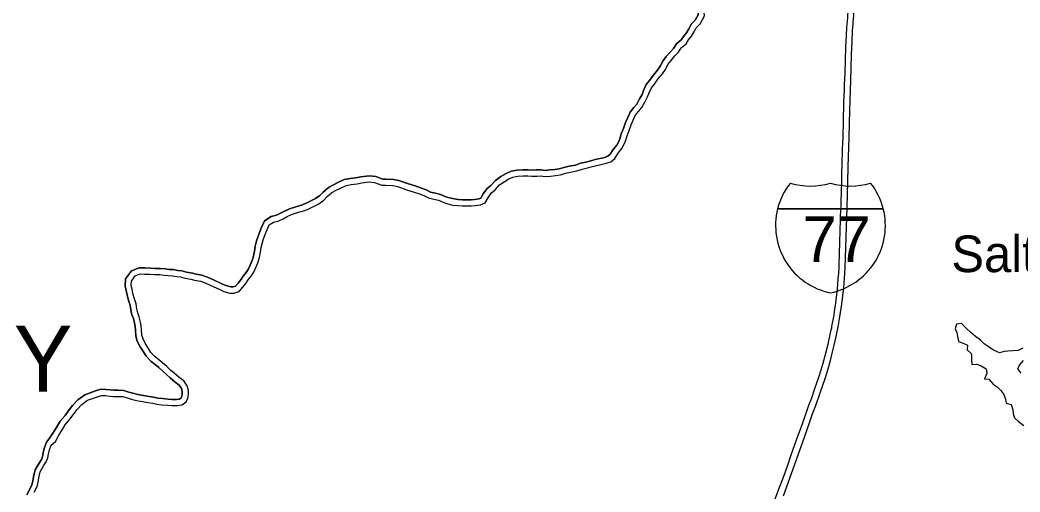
# Model space of a CAD drawing. Extents: x -29.6 to 34, y 0 to 22.
# Drawn here: x -24.702 to -22.275, y 9.402 to 10.547 of the extents above; entities that cross this region are included whole.
import ezdxf

# ---------------------------------------------------------------- set-up
doc = ezdxf.new("R2010")
doc.units = 0
for name, color, linetype in [('GM_X_Interstate_Route', 7, 'Continuous'), ('GM_X_Interstate_Shield', 7, 'Continuous'), ('GM_X_Major_Lake', 7, 'Continuous'), ('GM_X_Major_Lake_Text', 7, 'Continuous'), ('GM_X_Major_River', 7, 'Continuous'), ('GM_X_Township_Text', 7, 'Continuous')]:
    doc.layers.add(name, color=color, linetype=linetype)

msp = doc.modelspace()

# ---------------------------------------------------------------- linework, layer by layer
at = {"layer": 'GM_X_Interstate_Route'}
for points in [[(-22.6803, 10.5356), (-22.6799, 10.5406), (-22.6784, 10.5577), (-22.678, 10.562), (-22.6751, 10.5887), (-22.6714, 10.6173), (-22.6679, 10.6412), (-22.664, 10.6646), (-22.6599, 10.6866), (-22.6555, 10.7085), (-22.6498, 10.7343), (-22.6441, 10.758), (-22.6383, 10.7799), (-22.6335, 10.7978), (-22.627, 10.8194), (-22.6199, 10.8434), (-22.6114, 10.8677), (-22.6038, 10.8899)], [(-22.6947, 10.5356), (-22.6933, 10.5523), (-22.6926, 10.5587), (-22.6906, 10.5784), (-22.6882, 10.5986), (-22.6874, 10.605), (-22.6836, 10.6332), (-22.6802, 10.6557), (-22.6764, 10.6775), (-22.6716, 10.702), (-22.6662, 10.7271), (-22.6578, 10.7627), (-22.6532, 10.7809)], [(-22.8701, 9.3824), (-22.8592, 9.4114), (-22.8494, 9.4378), (-22.8379, 9.4695), (-22.8309, 9.4893), (-22.8164, 9.5305), (-22.8032, 9.5673), (-22.7872, 9.6122), (-22.7807, 9.6298), (-22.7727, 9.6525), (-22.7633, 9.6802), (-22.7576, 9.6979), (-22.7518, 9.7177), (-22.7465, 9.7385), (-22.7409, 9.7603), (-22.7355, 9.7839), (-22.7331, 9.7948), (-22.732, 9.7999), (-22.7316, 9.8022), (-22.7298, 9.8119), (-22.7286, 9.8188), (-22.727, 9.8268), (-22.7265, 9.8303), (-22.725, 9.8401), (-22.7228, 9.8545), (-22.7213, 9.8672), (-22.7197, 9.8805), (-22.7184, 9.8939), (-22.7172, 9.9066), (-22.7162, 9.9188), (-22.7151, 9.9322), (-22.7142, 9.9467), (-22.7137, 9.9595), (-22.7131, 9.9735), (-22.7128, 9.9869), (-22.7122, 10.0003), (-22.712, 10.0148), (-22.7114, 10.0276), (-22.7113, 10.0422), (-22.7106, 10.0555), (-22.7104, 10.0689), (-22.7097, 10.0852), (-22.7093, 10.0968), (-22.7091, 10.1108), (-22.7084, 10.1242), (-22.7083, 10.1353), (-22.7078, 10.1486), (-22.7075, 10.162), (-22.7072, 10.1789), (-22.7067, 10.1929), (-22.7064, 10.2074), (-22.7058, 10.2208), (-22.7056, 10.2336), (-22.705, 10.2476), (-22.7045, 10.2615), (-22.7043, 10.2749), (-22.7038, 10.29), (-22.7036, 10.3017), (-22.7031, 10.3174), (-22.7028, 10.3308), (-22.7024, 10.3471), (-22.7018, 10.3622), (-22.7014, 10.3773), (-22.7007, 10.3913), (-22.7003, 10.4041), (-22.6998, 10.418), (-22.6989, 10.4495), (-22.6978, 10.4815), (-22.6965, 10.5082), (-22.6952, 10.5291), (-22.6947, 10.5356)], [(-22.8492, 9.3926), (-22.8184, 9.4781), (-22.7974, 9.5373), (-22.7851, 9.5719), (-22.7784, 9.5912), (-22.7723, 9.6075), (-22.7676, 9.6213), (-22.7618, 9.6372), (-22.7583, 9.6473), (-22.7551, 9.6564), (-22.7474, 9.6796), (-22.7409, 9.7008), (-22.7352, 9.7209), (-22.7298, 9.7418), (-22.7259, 9.7582), (-22.7212, 9.7792), (-22.7166, 9.802), (-22.7129, 9.8221), (-22.7104, 9.837), (-22.7073, 9.8577), (-22.7047, 9.8779), (-22.7027, 9.8982), (-22.701, 9.9208), (-22.6996, 9.9452), (-22.6977, 9.9952), (-22.6949, 10.093), (-22.6929, 10.1541), (-22.6919, 10.1908), (-22.69, 10.2618), (-22.6879, 10.3276), (-22.686, 10.3997), (-22.6841, 10.4626), (-22.6828, 10.4946), (-22.6814, 10.5208), (-22.6803, 10.5356)]]:
    msp.add_lwpolyline(points, dxfattribs=at)
at = {"layer": 'GM_X_Interstate_Shield'}
for p, q in [((-22.8631, 10.0888), (-22.607, 10.0888)), ((-22.607, 10.0888), (-22.8631, 10.0888)), ((-22.607, 10.0888), (-22.8631, 10.0888))]:
    msp.add_line(p, q, dxfattribs=at)
for centre, start, end in [((-22.7018, 10.048), 141.669, 165.8066), ((-22.7837, 10.3104), 253.0091, 286.9909), ((-22.6864, 10.3104), 253.0091, 286.9909), ((-22.7683, 10.048), 14.1934, 38.331), ((-22.7018, 10.048), 165.8066, 258.463), ((-22.7683, 10.048), 281.537, 14.1934)]:
    msp.add_arc(centre, 0.1665, start, end, dxfattribs=at)
at = {"layer": 'GM_X_Major_Lake'}
for points in [[(-22.2682, 9.7509), (-22.2799, 9.7451), (-22.2927, 9.7439), (-22.3044, 9.7435), (-22.3136, 9.7423), (-22.3253, 9.7397), (-22.3395, 9.7457), (-22.3502, 9.7527), (-22.362, 9.7615), (-22.3713, 9.7703), (-22.3835, 9.7787), (-22.3949, 9.7883), (-22.406, 9.7992), (-22.4175, 9.8101), (-22.4292, 9.8086), (-22.4323, 9.7976), (-22.4283, 9.7883), (-22.4268, 9.7788), (-22.4242, 9.7667), (-22.4132, 9.7625), (-22.4028, 9.7576), (-22.4031, 9.7462), (-22.3931, 9.7367), (-22.3926, 9.7228), (-22.3918, 9.7111), (-22.3808, 9.7115), (-22.3698, 9.7077), (-22.3569, 9.7007), (-22.3554, 9.689), (-22.3614, 9.6765), (-22.3507, 9.6755), (-22.3403, 9.6635), (-22.331, 9.6572), (-22.3221, 9.648), (-22.3142, 9.6384), (-22.3105, 9.6271), (-22.309, 9.6175), (-22.2966, 9.6137), (-22.2926, 9.6009), (-22.2921, 9.5917), (-22.2885, 9.5814), (-22.2785, 9.5726), (-22.266, 9.5634)], [(-22.2723, 9.69), (-22.2806, 9.7006), (-22.2764, 9.7095), (-22.2666, 9.721)]]:
    msp.add_lwpolyline(points, dxfattribs=at)
at = {"layer": 'GM_X_Major_River'}
for points in [[(-23.0734, 10.5356), (-23.073, 10.5364), (-23.0632, 10.5463), (-23.0591, 10.5534), (-23.0559, 10.5593), (-23.0563, 10.5627), (-23.059, 10.5739)], [(-23.0583, 10.5711), (-23.0563, 10.5627), (-23.0559, 10.5593), (-23.0591, 10.5534), (-23.0632, 10.5463), (-23.073, 10.5364), (-23.0734, 10.5356)], [(-23.0529, 10.5356), (-23.0513, 10.5372), (-23.0461, 10.5461), (-23.0405, 10.5565), (-23.0416, 10.5654), (-23.0446, 10.5774)], [(-23.0734, 10.5356), (-23.0788, 10.5255), (-23.0844, 10.5159), (-23.0915, 10.5069), (-23.0967, 10.4991), (-23.1083, 10.4887), (-23.1157, 10.4778), (-23.1235, 10.4695), (-23.1336, 10.4581), (-23.142, 10.4467), (-23.1485, 10.4344), (-23.1547, 10.4247), (-23.1654, 10.412), (-23.1739, 10.3998), (-23.182, 10.3899), (-23.1887, 10.3759), (-23.1923, 10.3663), (-23.1982, 10.3557), (-23.2052, 10.3426), (-23.212, 10.3341), (-23.2214, 10.3229), (-23.2271, 10.3098), (-23.2322, 10.298), (-23.2375, 10.2838), (-23.2426, 10.2705), (-23.2462, 10.2582), (-23.2497, 10.2507), (-23.2538, 10.2433), (-23.2626, 10.2323), (-23.2698, 10.221), (-23.2757, 10.2161), (-23.2862, 10.2127), (-23.2945, 10.2103), (-23.3061, 10.2081), (-23.3162, 10.2054), (-23.3283, 10.2022), (-23.342, 10.1991), (-23.354, 10.1949), (-23.3688, 10.1924), (-23.3822, 10.1892), (-23.3933, 10.1857), (-23.4038, 10.1841), (-23.4161, 10.1829), (-23.4273, 10.1819), (-23.4369, 10.1836), (-23.4484, 10.1831), (-23.459, 10.1827), (-23.4686, 10.1836), (-23.4813, 10.1832), (-23.4956, 10.1827), (-23.5101, 10.1799), (-23.522, 10.1745), (-23.535, 10.1669), (-23.5478, 10.1576), (-23.5589, 10.1452), (-23.5687, 10.1375), (-23.5778, 10.1246), (-23.5833, 10.1148), (-23.5883, 10.1129), (-23.5987, 10.1113), (-23.6069, 10.1106), (-23.617, 10.1105), (-23.628, 10.1105), (-23.6381, 10.1114), (-23.6485, 10.1126), (-23.6593, 10.115), (-23.6681, 10.118), (-23.6816, 10.1235), (-23.6938, 10.1266), (-23.7055, 10.1292), (-23.7157, 10.1347), (-23.7273, 10.139), (-23.743, 10.144), (-23.7593, 10.1491), (-23.7708, 10.1535), (-23.7821, 10.1575), (-23.7951, 10.1599), (-23.8136, 10.1609), (-23.8211, 10.1608), (-23.8383, 10.1668), (-23.8547, 10.1688), (-23.8745, 10.1666), (-23.8865, 10.1637), (-23.9002, 10.1622), (-23.9149, 10.1596), (-23.9307, 10.1525), (-23.9413, 10.1471), (-23.9533, 10.1401), (-23.9664, 10.1293), (-23.9742, 10.1207), (-23.9843, 10.1134), (-23.994, 10.1086), (-24.0069, 10.1025), (-24.016, 10.0984), (-24.0327, 10.0938), (-24.0481, 10.0884)], [(-24.0477, 10.0885), (-24.0327, 10.0938), (-24.016, 10.0984), (-24.0069, 10.1025), (-23.994, 10.1086), (-23.9843, 10.1134), (-23.9742, 10.1207), (-23.9664, 10.1293), (-23.9533, 10.1401), (-23.9413, 10.1471), (-23.9307, 10.1525), (-23.9149, 10.1596), (-23.9002, 10.1622), (-23.8865, 10.1637), (-23.8745, 10.1666), (-23.8547, 10.1688), (-23.8383, 10.1668), (-23.8211, 10.1608), (-23.8136, 10.1609), (-23.7951, 10.1599), (-23.7821, 10.1575), (-23.7708, 10.1535), (-23.7593, 10.1491), (-23.743, 10.144), (-23.7273, 10.139), (-23.7157, 10.1347), (-23.7055, 10.1292), (-23.6938, 10.1266), (-23.6816, 10.1235), (-23.6681, 10.118), (-23.6593, 10.115), (-23.6485, 10.1126), (-23.6381, 10.1114), (-23.628, 10.1105), (-23.617, 10.1105), (-23.6069, 10.1106), (-23.5987, 10.1113), (-23.5883, 10.1129), (-23.5833, 10.1148), (-23.5778, 10.1246), (-23.5687, 10.1375), (-23.5589, 10.1452), (-23.5478, 10.1576), (-23.535, 10.1669), (-23.522, 10.1745), (-23.5101, 10.1799), (-23.4956, 10.1827), (-23.4813, 10.1832), (-23.4686, 10.1836), (-23.459, 10.1827), (-23.4484, 10.1831), (-23.4369, 10.1836), (-23.4273, 10.1819), (-23.4161, 10.1829), (-23.4038, 10.1841), (-23.3933, 10.1857), (-23.3822, 10.1892), (-23.3688, 10.1924), (-23.354, 10.1949), (-23.342, 10.1991), (-23.3283, 10.2022), (-23.3162, 10.2054), (-23.3061, 10.2081), (-23.2945, 10.2103), (-23.2862, 10.2127), (-23.2757, 10.2161), (-23.2698, 10.221), (-23.2626, 10.2323), (-23.2538, 10.2433), (-23.2497, 10.2507), (-23.2462, 10.2582), (-23.2426, 10.2705), (-23.2375, 10.2838), (-23.2322, 10.298), (-23.2271, 10.3098), (-23.2214, 10.3229), (-23.212, 10.3341), (-23.2052, 10.3426), (-23.1982, 10.3557), (-23.1923, 10.3663), (-23.1887, 10.3759), (-23.182, 10.3899), (-23.1739, 10.3998), (-23.1654, 10.412), (-23.1547, 10.4247), (-23.1485, 10.4344), (-23.142, 10.4467), (-23.1336, 10.4581), (-23.1235, 10.4695), (-23.1157, 10.4778), (-23.1083, 10.4887), (-23.0967, 10.4991), (-23.0915, 10.5069), (-23.0844, 10.5159), (-23.0788, 10.5255), (-23.0734, 10.5356)], [(-24.0427, 10.0745), (-24.0282, 10.0796), (-24.0109, 10.0843), (-24.0006, 10.089), (-23.9875, 10.0952), (-23.9766, 10.1006), (-23.9642, 10.1096), (-23.9561, 10.1186), (-23.9448, 10.1279), (-23.9342, 10.134), (-23.9243, 10.1391), (-23.9105, 10.1452), (-23.8981, 10.1475), (-23.8839, 10.149), (-23.8719, 10.1519), (-23.8549, 10.1539), (-23.8417, 10.1522), (-23.8235, 10.1459), (-23.814, 10.146), (-23.7969, 10.1451), (-23.7859, 10.143), (-23.7759, 10.1396), (-23.7642, 10.135), (-23.7474, 10.1298), (-23.7321, 10.125), (-23.7218, 10.1211), (-23.7108, 10.1152), (-23.6972, 10.1121), (-23.6862, 10.1093), (-23.6734, 10.1041), (-23.6634, 10.1006), (-23.651, 10.0979), (-23.6396, 10.0965), (-23.6286, 10.0956), (-23.6169, 10.0957), (-23.6062, 10.0958), (-23.597, 10.0965), (-23.5846, 10.0984), (-23.5729, 10.1028), (-23.5652, 10.1167), (-23.5578, 10.1271), (-23.5487, 10.1343), (-23.5378, 10.1465), (-23.5268, 10.1544), (-23.5152, 10.1612), (-23.5056, 10.1656), (-23.4939, 10.1678), (-23.4808, 10.1683), (-23.4691, 10.1687), (-23.4595, 10.1678), (-23.4478, 10.1682), (-23.4378, 10.1686), (-23.4279, 10.1669), (-23.4147, 10.1681), (-23.402, 10.1693), (-23.3899, 10.1712), (-23.3782, 10.1748), (-23.3658, 10.1778), (-23.3502, 10.1804), (-23.3378, 10.1848), (-23.3247, 10.1877), (-23.3123, 10.191), (-23.3028, 10.1936), (-23.2911, 10.1958), (-23.2819, 10.1984), (-23.2684, 10.2028), (-23.2585, 10.2111), (-23.2505, 10.2236), (-23.2413, 10.235), (-23.2364, 10.244), (-23.2322, 10.2529), (-23.2284, 10.2657), (-23.2236, 10.2786), (-23.2184, 10.2925), (-23.2135, 10.3039), (-23.2086, 10.315), (-23.2005, 10.3247), (-23.1928, 10.3343), (-23.1851, 10.3486), (-23.1788, 10.3601), (-23.175, 10.37), (-23.1694, 10.3818), (-23.162, 10.3908), (-23.1536, 10.403), (-23.1427, 10.4158), (-23.1357, 10.4269), (-23.1294, 10.4387), (-23.122, 10.4487), (-23.1125, 10.4595), (-23.104, 10.4685), (-23.097, 10.4788), (-23.0854, 10.4892), (-23.0794, 10.4982), (-23.0721, 10.5075), (-23.0657, 10.5182), (-23.0609, 10.5275), (-23.0529, 10.5356)], [(-24.0481, 10.0884), (-24.0602, 10.0832), (-24.0698, 10.0779), (-24.0791, 10.0733), (-24.0922, 10.0698), (-24.1085, 10.0598), (-24.1165, 10.0421), (-24.1209, 10.0311), (-24.1246, 10.0202), (-24.1274, 10.011), (-24.1313, 9.9979), (-24.1327, 9.9863), (-24.1352, 9.974), (-24.1385, 9.9629), (-24.143, 9.952), (-24.1477, 9.9418), (-24.1525, 9.9343), (-24.1603, 9.9253), (-24.1661, 9.9161), (-24.1724, 9.9081), (-24.1786, 9.9011), (-24.1846, 9.8991), (-24.1904, 9.8993), (-24.2022, 9.9023), (-24.2118, 9.907), (-24.2321, 9.9161), (-24.2468, 9.9231), (-24.2605, 9.9275), (-24.2744, 9.9299), (-24.2833, 9.9327), (-24.2976, 9.9352), (-24.3092, 9.938), (-24.3186, 9.9394), (-24.3302, 9.9412), (-24.3407, 9.9415), (-24.3498, 9.9428), (-24.3617, 9.9439), (-24.3744, 9.9441), (-24.3852, 9.9447), (-24.3989, 9.9454), (-24.4126, 9.9457), (-24.4311, 9.9379), (-24.446, 9.9188), (-24.4464, 9.9011), (-24.4442, 9.8905), (-24.442, 9.8799), (-24.4384, 9.866), (-24.4341, 9.855), (-24.433, 9.8435), (-24.4299, 9.8316), (-24.4264, 9.8222), (-24.4237, 9.8109), (-24.4221, 9.8031), (-24.4217, 9.7946), (-24.4204, 9.7799), (-24.4172, 9.7677), (-24.4103, 9.7535), (-24.4023, 9.7414), (-24.3959, 9.7312), (-24.3836, 9.7182), (-24.374, 9.711), (-24.3651, 9.7036), (-24.3554, 9.695), (-24.346, 9.6865), (-24.337, 9.6786), (-24.3248, 9.6681), (-24.3154, 9.6609), (-24.3101, 9.6529), (-24.308, 9.6456), (-24.308, 9.6399), (-24.3089, 9.6337), (-24.3103, 9.6303), (-24.3144, 9.6273), (-24.3215, 9.6262), (-24.3327, 9.6265), (-24.3421, 9.6271), (-24.3557, 9.6283), (-24.3676, 9.6296), (-24.3767, 9.6315), (-24.3886, 9.6336), (-24.4017, 9.636), (-24.4159, 9.6386), (-24.428, 9.6416), (-24.4374, 9.6442), (-24.4495, 9.6483), (-24.4637, 9.6486), (-24.4741, 9.6485), (-24.4825, 9.6494), (-24.493, 9.6505), (-24.5055, 9.6508), (-24.5181, 9.6471), (-24.531, 9.6426), (-24.5447, 9.6374), (-24.5616, 9.625), (-24.5744, 9.6116), (-24.5847, 9.5976), (-24.5922, 9.5876), (-24.6039, 9.5734), (-24.6129, 9.5586), (-24.62, 9.5469), (-24.6297, 9.5322)], [(-24.6297, 9.5322), (-24.62, 9.5469), (-24.6129, 9.5586), (-24.6039, 9.5734), (-24.5922, 9.5876), (-24.5847, 9.5976), (-24.5744, 9.6116), (-24.5616, 9.625), (-24.5447, 9.6374), (-24.531, 9.6426), (-24.5181, 9.6471), (-24.5055, 9.6508), (-24.493, 9.6505), (-24.4825, 9.6494), (-24.4741, 9.6485), (-24.4637, 9.6486), (-24.4495, 9.6483), (-24.4374, 9.6442), (-24.428, 9.6416), (-24.4159, 9.6386), (-24.4017, 9.636), (-24.3886, 9.6336), (-24.3767, 9.6315), (-24.3676, 9.6296), (-24.3557, 9.6283), (-24.3421, 9.6271), (-24.3327, 9.6265), (-24.3215, 9.6262), (-24.3144, 9.6273), (-24.3103, 9.6303), (-24.3089, 9.6337), (-24.308, 9.6399), (-24.308, 9.6456), (-24.3101, 9.6529), (-24.3154, 9.6609), (-24.3248, 9.6681), (-24.337, 9.6786), (-24.346, 9.6865), (-24.3554, 9.695), (-24.3651, 9.7036), (-24.374, 9.711), (-24.3836, 9.7182), (-24.3959, 9.7312), (-24.4023, 9.7414), (-24.4103, 9.7535), (-24.4172, 9.7677), (-24.4204, 9.7799), (-24.4217, 9.7946), (-24.4221, 9.8031), (-24.4237, 9.8109), (-24.4264, 9.8222), (-24.4299, 9.8316), (-24.433, 9.8435), (-24.4341, 9.855), (-24.4384, 9.866), (-24.442, 9.8799), (-24.4442, 9.8905), (-24.4464, 9.9011), (-24.446, 9.9188), (-24.4311, 9.9379), (-24.4126, 9.9457), (-24.3989, 9.9454), (-24.3852, 9.9447), (-24.3744, 9.9441), (-24.3617, 9.9439), (-24.3498, 9.9428), (-24.3407, 9.9415), (-24.3302, 9.9412), (-24.3186, 9.9394), (-24.3092, 9.938), (-24.2976, 9.9352), (-24.2833, 9.9327), (-24.2744, 9.9299), (-24.2605, 9.9275), (-24.2468, 9.9231), (-24.2321, 9.9161), (-24.2118, 9.907), (-24.2022, 9.9023), (-24.1904, 9.8993), (-24.1846, 9.8991), (-24.1786, 9.9011), (-24.1724, 9.9081), (-24.1661, 9.9161), (-24.1603, 9.9253), (-24.1525, 9.9343), (-24.1477, 9.9418), (-24.143, 9.952), (-24.1385, 9.9629), (-24.1352, 9.974), (-24.1327, 9.9863), (-24.1313, 9.9979), (-24.1274, 10.011), (-24.1246, 10.0202), (-24.1209, 10.0311), (-24.1165, 10.0421), (-24.1085, 10.0598), (-24.0922, 10.0698), (-24.0791, 10.0733), (-24.0698, 10.0779), (-24.0602, 10.0832), (-24.0486, 10.0881)], [(-24.6157, 9.5242), (-24.6072, 9.5394), (-24.6002, 9.5508), (-24.5918, 9.5648), (-24.5805, 9.5784), (-24.5728, 9.5887), (-24.563, 9.602), (-24.5517, 9.6138), (-24.5376, 9.6242), (-24.5259, 9.6286), (-24.5135, 9.633), (-24.5036, 9.6359), (-24.494, 9.6356), (-24.484, 9.6346), (-24.4748, 9.6336), (-24.4638, 9.6337), (-24.4521, 9.6334), (-24.4418, 9.63), (-24.4318, 9.6272), (-24.419, 9.6241), (-24.4044, 9.6213), (-24.3913, 9.619), (-24.3795, 9.6169), (-24.3699, 9.6149), (-24.3571, 9.6135), (-24.3433, 9.6122), (-24.3333, 9.6116), (-24.3205, 9.6113), (-24.3085, 9.6132), (-24.2982, 9.6207), (-24.2944, 9.6297), (-24.2931, 9.6389), (-24.2931, 9.6478), (-24.2964, 9.6592), (-24.3043, 9.6712), (-24.3154, 9.6797), (-24.3272, 9.6899), (-24.3361, 9.6976), (-24.3454, 9.7061), (-24.3555, 9.7149), (-24.3648, 9.7227), (-24.3737, 9.7294), (-24.3841, 9.7403), (-24.3898, 9.7495), (-24.3974, 9.7608), (-24.4031, 9.7729), (-24.4057, 9.7825), (-24.4069, 9.7956), (-24.4073, 9.8049), (-24.4092, 9.8141), (-24.4121, 9.8265), (-24.4157, 9.8361), (-24.4183, 9.846), (-24.4195, 9.8585), (-24.4242, 9.8705), (-24.4275, 9.8833), (-24.4297, 9.8936), (-24.4315, 9.9025), (-24.4313, 9.9135), (-24.4218, 9.9257), (-24.4097, 9.9308), (-24.3994, 9.9305), (-24.3859, 9.9299), (-24.3749, 9.9293), (-24.3625, 9.929), (-24.3515, 9.928), (-24.3419, 9.9267), (-24.3316, 9.9264), (-24.3209, 9.9247), (-24.312, 9.9233), (-24.3007, 9.9206), (-24.2868, 9.9182), (-24.2779, 9.9154), (-24.264, 9.913), (-24.2523, 9.9092), (-24.2384, 9.9026), (-24.2181, 9.8935), (-24.2074, 9.8882), (-24.1924, 9.8844), (-24.1825, 9.8842), (-24.1701, 9.8882), (-24.161, 9.8985), (-24.1539, 9.9075), (-24.1483, 9.9164), (-24.1406, 9.9254), (-24.1346, 9.9347), (-24.1294, 9.9461), (-24.1245, 9.9579), (-24.1207, 9.9704), (-24.118, 9.9839), (-24.1166, 9.9949), (-24.1132, 10.0067), (-24.1104, 10.0156), (-24.107, 10.026), (-24.1028, 10.0363), (-24.0969, 10.0495), (-24.0863, 10.056), (-24.0739, 10.0593), (-24.0629, 10.0647), (-24.0537, 10.0698), (-24.0427, 10.0745)], [(-24.685, 9.3946), (-24.6786, 9.4071), (-24.6727, 9.4191), (-24.6707, 9.4283), (-24.669, 9.4385), (-24.6646, 9.4556), (-24.6555, 9.4718), (-24.6498, 9.4804), (-24.6472, 9.488), (-24.6456, 9.4966), (-24.6429, 9.5076), (-24.6373, 9.5229), (-24.6297, 9.5322)], [(-24.6297, 9.5322), (-24.6373, 9.5229), (-24.6429, 9.5076), (-24.6456, 9.4966), (-24.6472, 9.488), (-24.6498, 9.4804), (-24.6555, 9.4718), (-24.6646, 9.4556), (-24.669, 9.4385), (-24.6707, 9.4283), (-24.6727, 9.4191), (-24.6786, 9.4071), (-24.685, 9.3946)], [(-24.6669, 9.4013), (-24.6603, 9.4148), (-24.6579, 9.4258), (-24.6562, 9.4358), (-24.6524, 9.4507), (-24.6443, 9.465), (-24.638, 9.4746), (-24.6345, 9.4846), (-24.6328, 9.4939), (-24.6304, 9.5038), (-24.6262, 9.5152), (-24.6157, 9.5242)]]:
    msp.add_lwpolyline(points, dxfattribs=at)

# ---------------------------------------------------------------- texts
at = {"layer": 'GM_X_Interstate_Shield'}
msp.add_text('77', height=0.11097, dxfattribs=at).set_placement((-22.8025, 9.9598))
at = {"layer": 'GM_X_Major_Lake_Text'}
msp.add_text('Salt Fork', height=0.08878, rotation=0.0035, dxfattribs=at).set_placement((-22.4417, 9.9351))
at = {"layer": 'GM_X_Township_Text'}
msp.add_text('LIBERTY', height=0.1598, rotation=0, dxfattribs=at).set_placement((-25.465, 9.6452))

doc.saveas('drawing.dxf')
